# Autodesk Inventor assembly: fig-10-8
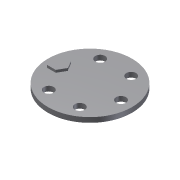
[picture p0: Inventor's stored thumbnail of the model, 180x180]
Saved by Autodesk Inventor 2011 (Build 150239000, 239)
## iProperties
Created: 2008-05
Part Number: fig-10-8
Document SubType Name: Assembly
Designer: CADCIM
Author: CADCIM
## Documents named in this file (3)
- C:\Users\CADSoft\Desktop\part files\c10-inv-2011-prt\fig-10-8.iam
- C:\Users\CADSoft\Desktop\inventor\c10-inv-2010-prt\c10\Part4.ipt
- C:\Users\CADSoft\Desktop\inventor\c10-inv-2010-prt\c10\Part5.ipt
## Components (2 placed, 2 different names)
1. Part4:1
2. Part5:1
